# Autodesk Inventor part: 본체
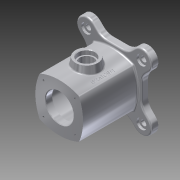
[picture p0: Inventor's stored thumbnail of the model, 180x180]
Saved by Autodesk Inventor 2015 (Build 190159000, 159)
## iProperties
Created: 2016-05
Part Number: 본체
Material: 알루미늄 6061
Document SubType Name: Modeling
Designer: Administrator
Density: 2.7 g/cm^3
Appearance: 알루미늄 - 평지
Mass: 1104.93 g
Surface Area: 865.283 cm^2
Volume: 409.235 cm^3
Author: Administrator
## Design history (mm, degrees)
sketch "스케치1" dims "d0" = 70
  geometry: L1 (49, 49)-(-49, 49); L2 (-49, 49)-(-49, -49); L3 (-49, -49)-(49, -49); L4 (49, -49)-(49, 49); L5 (49, 49)-(-49, -49); L6 (-49, 49)-(49, -49); L7 (0, -70)-(0, 70); L8 (-70, 0)-(70, 0); L9 (0, 0)-(-60.519, 60.519); L10 (0, 0)-(85.587, 0); L11 (-49, 23.544)-(-62.225, 36.77); L12 (-23.544, 49)-(-36.77, 62.225); L13 (-49, -23.544)-(-62.225, -36.77); L14 (-23.544, -49)-(-36.77, -62.225); L15 (49, 23.544)-(62.225, 36.77); L16 (23.544, 49)-(36.77, 62.225); L17 (23.544, -49)-(36.77, -62.225); L18 (49, -23.544)-(62.225, -36.77); L19 (23.544, 49)-(49, 49); L20 (49, 49)-(49, 23.544); L21 (49, -23.544)-(49, -49); L22 (23.544, -49)-(49, -49); L23 (-49, -23.544)-(-49, -49); L24 (-49, -49)-(-23.544, -49); A1 r 18 centre (-49.497, 49.497) between (-35.239, 60.483) and (-60.483, 35.239); A2 r 18 centre (-49.497, -49.497) between (-60.483, -35.239) and (-35.239, -60.483); A3 r 18 centre (49.497, 49.497) between (60.483, 35.239) and (35.239, 60.483); A4 r 18 centre (49.497, -49.497) between (35.239, -60.483) and (60.483, -35.239); 1 further point
  constraints: 48 end point, 21 symmetric about line, 16 point on circle, 5 collinear, 5 point on line, 4 centre point, 4 midpoint, 3 horizontal, 2 parallel, 1 coincident, 1 equal length, 1 perpendicular, 1 vertical, 12 other
  dimensions: "d1" = 98 distance of L3.end L2.end; "d2" = 98 distance of L2.end L1.end; "d4" = 135 deg angle of L10 L9; "d5" = 18 radius of A1; "d6" = 36 diameter of L11 L9; "d7" = 36 diameter of L12 L9
extrude "돌출1" new body sketch "스케치1" distance "d8" = 12; taper "d9" = 0 deg
fillet "모깎기1" dims "d10" = 25
sketch "스케치2"
  geometry: A1 r 18 centre (49.497, -49.497) between (36.77, -62.225) and (62.225, -36.77) reference; 2 further points
  constraints: 1 coincident
hole "구멍1" sketch "스케치2" at (49.497, -49.497) diameter "d11" = 10; stored, may be unused: countersink angle "d15" = 90 deg, drill point angle "d17" = 118 deg; dims "d12" = 6, "d13" = 18, "d14" = 4, "d16" = 15
sketch "스케치3"
  geometry: L1 (35.355, 35.355)-(-35.355, -35.355); L2 (0, 0)-(50, 0); L3 (35.355, -35.355)-(-35.355, 35.355); L4 (0, 0)-(50, 0); C1 r 43 at (0, 0); A1 r 50 centre (0, 0) between (-35.355, -35.355) and (35.355, 35.355); A2 r 85.579 centre (0, 42.579) between (-35.355, -35.355) and (35.355, -35.355); A3 r 85.579 centre (42.579, 0) between (-35.355, 35.355) and (-35.355, -35.355); A4 r 90.136 centre (0, -47.557) between (35.355, 35.355) and (-35.355, 35.355); A5 r 85.579 centre (-42.579, 0) between (35.355, -35.355) and (35.355, 35.355); 1 further point
  constraints: 13 point on circle, 8 end point, 6 centre point, 2 coincident, 2 horizontal, 2 midpoint
  dimensions: "d18" = 86 diameter of C1; "d20" = 100 diameter of A1; "d21" = 135 deg angle of L1 L2; "d22" = 135 deg angle of L4 L3; "d23" = 85.57874 radius of A2; "d24" = 85.57874 radius of A3; "d25" = 85.57874 radius of A5
extrude "돌출2" join sketch "스케치3" distance "d26" = 98; taper "d27" = 0 deg
fillet "모깎기2" dims "d28" = 3
fillet "모깎기3" dims "d29" = 3
fillet "모깎기4" dims "d30" = 3
node "작업 평면2"
sketch "스케치4"
  geometry: L1 (-64.497, 12)-(-38.891, 12) reference; C1 r 20 at (0, 61); 2 further points
  constraints: 1 centre point, 1 vertical alignment
  dimensions: "d32" = 40 diameter of C1; "d33" = 49 distance from line of L1 C1.centre
extrude "돌출3" join sketch "스케치4" distance "d34" = 30; taper "d35" = 10 deg
sketch "스케치5"
  geometry: C1 r 20 at (0, 0) reference; 2 further points
  constraints: 1 coincident
hole "구멍2" sketch "스케치5" at (0, 0) diameter "d36" = 25; stored, may be unused: countersink angle "d40" = 90 deg, drill point angle "d42" = 118 deg; dims "d37" = 6, "d38" = 30, "d39" = 8, "d41" = 30
sketch "스케치6"
  geometry: C1 r 25 at (0, 0); 1 further point
  constraints: 1 centre point, 1 coincident
  dimensions: "d43" = 50 diameter of C1
extrude "돌출4" cut sketch "스케치6" distance "d44" = 12; taper "d45" = 0 deg
sketch "스케치7"
  geometry: C1 r 25 at (0, 0) reference; C2 r 35 at (0, 0)
  constraints: 1 centre point, 1 coincident
  dimensions: "d46" = 70 diameter of C2
extrude "돌출5" cut sketch "스케치7" distance "d47" = 86; taper "d48" = 0 deg
sketch "스케치8"
  geometry: C1 r 25 at (0, 0); 1 further point
  constraints: 1 centre point, 1 coincident
  dimensions: "d49" = 50 diameter of C1
extrude "돌출6" cut sketch "스케치8" distance "d50" = 12; taper "d51" = 0 deg
fillet "모깎기5" dims "d52" = 3
chamfer "모따기1" distance "d53" = 1; stored, may be unused: second distance "d54" = 2, angle "d55" = 45 deg
sketch "스케치9" dims "d56" = 40
  geometry: L1 (0, 0)-(-28.284, -28.284); L2 (0, 0)-(40, 0); C1 r 26 at (0, 0) reference; 1 further point
  constraints: 4 end point, 2 coincident, 1 equal length, 1 horizontal, 3 other
  dimensions: "d57" = 135 deg angle of L1 L2
hole "구멍3" sketch "스케치9" at (-28.284, -28.284) diameter "d58" = 3.242; stored, may be unused: countersink angle "d62" = 90 deg, drill point angle "d64" = 118 deg; dims "d59" = 7, "d60" = 30, "d61" = 8, "d63" = 10
node "작업 평면3"
fillet "모깎기6" dims "d68" = 3
node "작업 평면4"
sketch "스케치10"
  geometry: L1 (34.285, 98)-(-34.248, 98) reference; L2 (0, -12)-(0.018, 98); 2 further points
  constraints: 2 coincident, 2 end point, 1 midpoint, 1 other
  dimensions: "d69" = 49 distance from line of L1 point (-28.99, 49); "d70" = 29 distance from line of L2 point (-28.99, 49)
feature "엠보싱1" sketch "스케치10" dims "d71" = 0.5, "d72" = 0
node "솔리드1"
mirror "대칭2"
mirror "대칭3"
pattern_circular "원형 패턴1" dims angle "d66" = 360 deg
mirror "대칭4"
other parameters: "d31" = -55
